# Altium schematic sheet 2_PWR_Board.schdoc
size 254 x 203 mm; Symbol: Altium_A; Device: Altium_A; SheetNumber: 1; SheetTotal: 5; @Page No: 2; @Page Count: 5; @Schematic Name: Balance_batt_protection_SolidState_3; @Project Name: BFMC_Power Board V2; @Board Name: greater0603 Dsample; @Update Date: 2024-08-30; @Page Name: PWR_Board; @Create Time: 10:15:35; @Update Time: 12:45:22; @Create Date: 2024-08-29
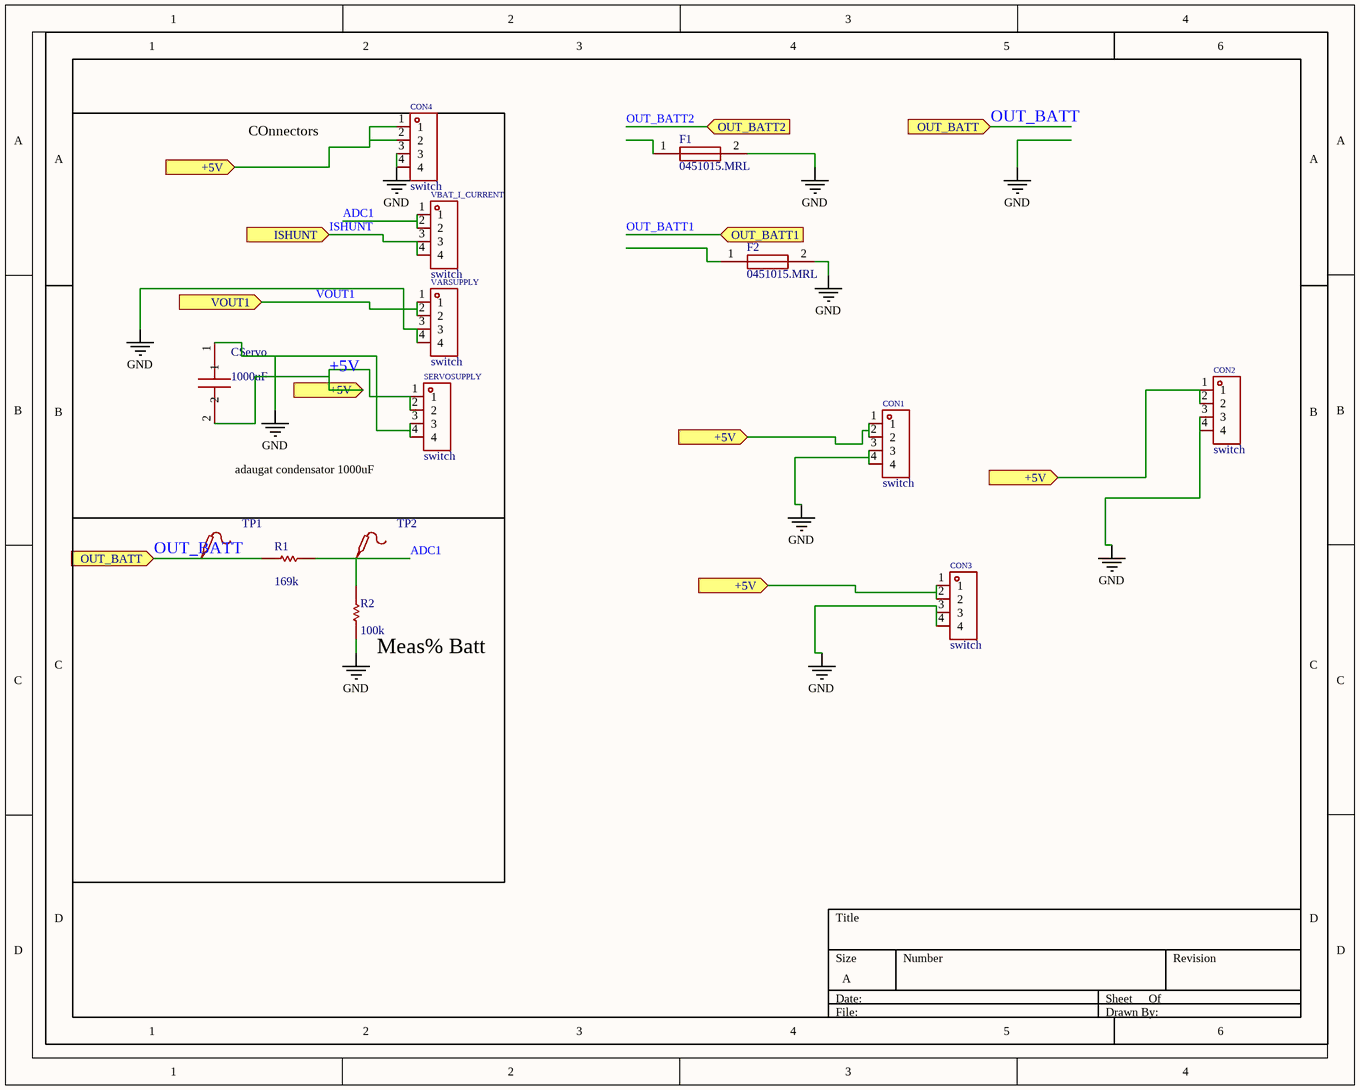
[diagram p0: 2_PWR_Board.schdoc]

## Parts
CON1  switch  [new connector]  (value not drawn)
CON2  switch  [new connector]  (value not drawn)
CON3  switch  [new connector]  (value not drawn)
CON4  switch  [new connector]  (value not drawn)
CServo  value 1000uF  [CAPAE1030X1050N]  (hidden comment: GCM188C71A225K)
F1  0451015.MRL  [FUSC6127X294N]  (value not drawn)
F2  0451015.MRL  [FUSC6127X294N]  (value not drawn)
R1  value 169k  [R0805_NEW]  (hidden comment: MCR03..PFX1051)
R2  value 100k  [R0603]  (hidden comment: MCR03...PFX7680)
SERVOSUPPLY  switch  [new connector]  (value not drawn)
TP1  Test-Point  [Test-Point-0.5mm]  (value not drawn)
TP2  Test-Point  [Test-Point-0.5mm]  (value not drawn)
VARSUPPLY  switch  [new connector]  (value not drawn)
VBAT_I_CURRENT  switch  [new connector]  (value not drawn)

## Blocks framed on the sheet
COnnectors: CON4 CServo SERVOSUPPLY VARSUPPLY VBAT_I_CURRENT
Meas% Batt: R1 R2 TP1 TP2

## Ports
+5V (in), ISHUNT (in), OUT_BATT1 (in), OUT_BATT2 (in), OUT_BATT (in), VOUT1 (in)

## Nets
GND: CON1.3 CON1.4 CON2.3 CON2.4 CON3.3 CON3.4 CON4.3 CON4.4 CServo.1 F1.2 F2.2 R2.2 SERVOSUPPLY.3 SERVOSUPPLY.4 VARSUPPLY.3 VARSUPPLY.4
+5V: CON1.1 CON1.2 CON2.1 CON2.2 CON3.1 CON3.2 CON4.1 CON4.2 CServo.2 SERVOSUPPLY.1 SERVOSUPPLY.2 ; port +5V
ADC1: R1.1 R2.1 TP2.1 VBAT_I_CURRENT.1 VBAT_I_CURRENT.2
ISHUNT: VBAT_I_CURRENT.3 VBAT_I_CURRENT.4 ; port ISHUNT
OUT_BATT: R1.2 TP1.1 ; port OUT_BATT
VOUT1: VARSUPPLY.1 VARSUPPLY.2 ; port VOUT1

Not connected (* = marked no-connect by the designer): F1 1; F2 1

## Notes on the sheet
- adaugat condensator 1000uF

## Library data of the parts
CON1-CON4 SERVOSUPPLY VARSUPPLY VBAT_I_CURRENT = HDR-F_2.54_1x4P: Manufacturer: BOOMELE(博穆精密); Symbol: 2.54-1*4P母; Convert to PCB: yes
CServo = GCM188C71A225K: C1608X7R1A225K08; Manufacturer Part Number: C1608X7R1A225K080AC; Manufacturer Name: TDK; Symbol: Cinx; Add into BOM: yes; Origin Footprint: CAPC1608X80N
F1 F2 = 0451015.MRL: Fuse; Manufacturer_Name: LITTELFUSE; Add into BOM: yes
R1 = MCR03..PFX1051: Resistor; Symbol: Res1; Origin Footprint 2: AXIAL-0.3; Add into BOM: yes; Origin Footprint 1: RESC1608X55N
R2 = MCR03...PFX7680: Resistor; Symbol: Res1; Origin Footprint 2: AXIAL-0.3; Add into BOM: yes; Origin Footprint 1: RESC1608X55N
TP1 TP2 = Test-Point: Test Point 测试点; Add into BOM: yes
